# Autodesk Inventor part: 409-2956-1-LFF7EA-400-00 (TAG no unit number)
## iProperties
Created: 2010-06
Part Number: 409-2956-1-LFF7EA-400-00 (TAG no unit number)
Material: 1/16"Thk PLASTIC
Document SubType Name: Modeling
Designer: S. Boerckel
Engineer: Steve Boerckel
Mass: 230.369 g
Surface Area: 3121.56 cm^2
Volume: 245.074 cm^3
Density: 0.94 g/cm^3
Description: TAG
SMR: =<Material>
Length: 20.000 in
Wide: 12.000 in
Thickness: 0.063 in
Author: S. Boerckel
Revision Number: 0
Subject: DEMIN WATER FORWARDING PUMP SKID-7EA
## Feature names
1. Extrusion1
2. Hole1
